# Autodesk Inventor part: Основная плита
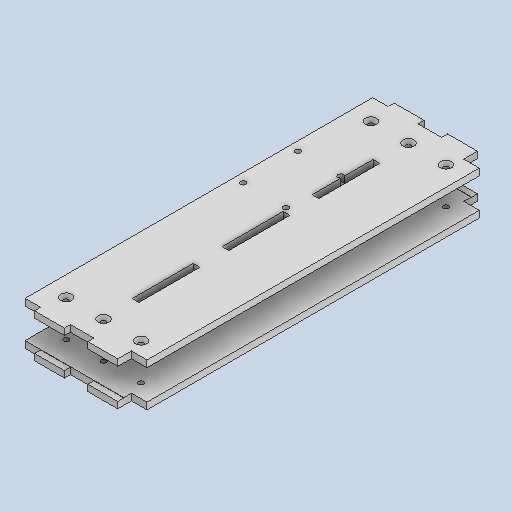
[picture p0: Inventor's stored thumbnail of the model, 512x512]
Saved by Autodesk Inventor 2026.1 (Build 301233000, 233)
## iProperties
Created: 2025-12
Part Number: Основная плита
Material: Типовые
Document SubType Name: Modeling
Designer: Yury Melnikov
Density: 1 g/cm^3
Appearance: Фанера — с эффектом атмосферных воздействий
Author: Yury Melnikov
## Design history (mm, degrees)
derived "Направляющие.ipt"
sketch "Эскиз1"
  geometry: L1 (39.69, -193)-(35.29, -193) reference; L2 (35.29, -193)-(35.29, -153) reference; L3 (35.29, -153)-(39.69, -153) reference; L4 (39.69, -153)-(39.69, -193) reference; L5 (39.69, -134)-(35.29, -134) reference; L6 (35.29, -134)-(35.29, -94) reference; L7 (35.29, -94)-(39.69, -94) reference; L8 (39.69, -94)-(39.69, -134) reference; L9 (39.69, -75)-(35.29, -75) reference; L10 (35.29, -75)-(35.29, -35) reference; L11 (35.29, -35)-(39.69, -35) reference; L12 (39.69, -35)-(39.69, -75) reference; L13 (64.78, 0)-(0, 0) reference; L14 (0, 0)-(0, -228) reference; L15 (64.78, -228)-(0, -228) reference; L16 (74.98, -5)-(74.98, -223) reference; L17 (0, 0)-(0, -228) reference; L18 (0, -114)-(74.98, -114); L19 (64.78, -223)-(74.98, -223) reference; L20 (74.98, -5)-(64.78, -5) reference; L21 (64.78, -5)-(64.78, 0) reference; L22 (64.78, -228)-(64.78, -223) reference; C1 r 1.65 at (62.08, -14) reference; C2 r 1.65 at (37.49, -14) reference; C3 r 1.65 at (12.9, -14) reference; C4 r 1.65 at (62.08, -214); C5 r 1.65 at (37.49, -214); C6 r 1.65 at (77.08, -214); C7 r 1.65 at (12.9, -214); 1 further point
  constraints: 4 centre point, 3 symmetric about line, 2 end point, 2 midpoint, 3 other
extrude "Выдавливание1" cut sketch "Эскиз1" distance "d1" = 10; taper "d2" = 0 deg
feature "Основная плита::Направляющие.ipt" dims "d0" = 10
tag "Элемент создания тегов1"
node "Спроецированная петля1"
node "Основная плита"
